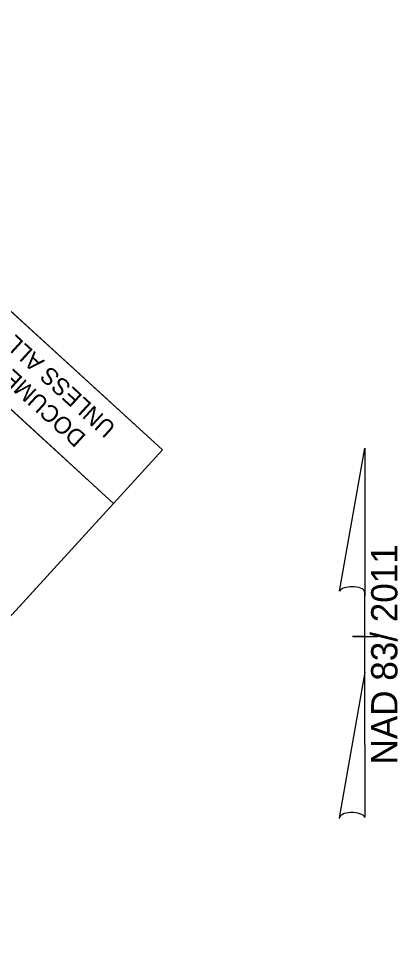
# Model space of a CAD drawing. Extents: x 475722 to 477703, y 499689 to 501633.
# Drawn here: x 475967.4 to 476091.2, y 500661.4 to 500963.2 of the extents above; entities that cross this region are included whole.
import ezdxf

# ---------------------------------------------------------------- set-up
doc = ezdxf.new("R2010")
doc.units = 0
for name, color, linetype in [('Prop North Arrow NAD83 for Plan Sheets CELL', 7, 'Continuous'), ('Sheet Clip Boundary CELL', 7, 'Continuous'), ('Sheet Plan CELL', 7, 'Continuous'), ('Sheet Sticker Exception Certification CELL', 7, 'Continuous')]:
    doc.layers.add(name, color=color, linetype=linetype)

msp = doc.modelspace()

# ---------------------------------------------------------------- linework, layer by layer
at = {"layer": 'Prop North Arrow NAD83 for Plan Sheets CELL'}
for p, q in [((476071.43, 500777.54), (476079.63, 500823.89)), ((476079.68, 500823.89), (476079.63, 500823.89)), ((476079.68, 500823.89), (476079.63, 500823.89)), ((476079.68, 500823.89), (476079.68, 500776.09)), ((476079.68, 500751.29), (476079.68, 500777.49)), ((476079.68, 500776.09), (476079.68, 500777.44)), ((476075.68, 500762.89), (476075.63, 500762.89)), ((476079.23, 500762.89), (476075.68, 500762.89)), ((476075.73, 500762.89), (476083.73, 500762.89)), ((476079.68, 500751.29), (476071.33, 500704.04)), ((476079.73, 500704.24), (476079.68, 500751.29))]:
    msp.add_line(p, q, dxfattribs=at)
for centre, start_param, end_param in [((476075.57, 500777.04), 0.216388, 2.908219), ((476075.57, 500703.87), 0.201328, 3.141593)]:
    msp.add_ellipse(centre, major_axis=(4.23, -0.03), ratio=0.461098, start_param=start_param, end_param=end_param, dxfattribs=at)
at = {"layer": 'Sheet Clip Boundary CELL'}
msp.add_lwpolyline([(475896.94, 500695.24), (476776.38, 499891.66), (476856.61, 499818.34), (476969.21, 499941.58), (477026.31, 500152.38), (477503.19, 500649.86), (476731.13, 501355.34), (476672.99, 501291.71), (476544.91, 501408.73), (475869.73, 500955.21), (476014.01, 500823.37)], close=True, dxfattribs=at)
at = {"layer": 'Sheet Plan CELL'}
msp.add_lwpolyline([(475922.29, 500722.98), (475848.43, 500790.47), (475924.32, 500873.53), (475998.16, 500806.03)], close=True, dxfattribs=at)
at = {"layer": 'Sheet Sticker Exception Certification CELL'}
for p, q in [((475866.34, 500958.31), (476014.01, 500823.37)), ((475866.34, 500958.31), (476014.01, 500823.37)), ((475998.16, 500806.03), (475850.49, 500940.96)), ((475998.16, 500806.03), (475850.49, 500940.96)), ((476014.01, 500823.37), (475998.16, 500806.03)), ((476014.01, 500823.37), (475998.16, 500806.03))]:
    msp.add_line(p, q, dxfattribs=at)

# ---------------------------------------------------------------- texts
at = {"layer": 'Prop North Arrow NAD83 for Plan Sheets CELL'}
msp.add_text('NAD 83/ 2011', height=8.5, rotation=90, dxfattribs=at).set_placement((476090.2, 500721.37))
at = {"layer": 'Sheet Sticker Exception Certification CELL'}
for s, p in [('UNLESS ALL SIGNATURES COMPLETED', (475999.26, 500830.95)), ('UNLESS ALL SIGNATURES COMPLETED', (475999.26, 500830.95)), ('DOCUMENT NOT CONSIDERED FINAL', (475989.58, 500827.88)), ('DOCUMENT NOT CONSIDERED FINAL', (475989.58, 500827.88))]:
    msp.add_text(s, height=5.5, rotation=137.58, dxfattribs=at).set_placement(p)

doc.saveas('drawing.dxf')
